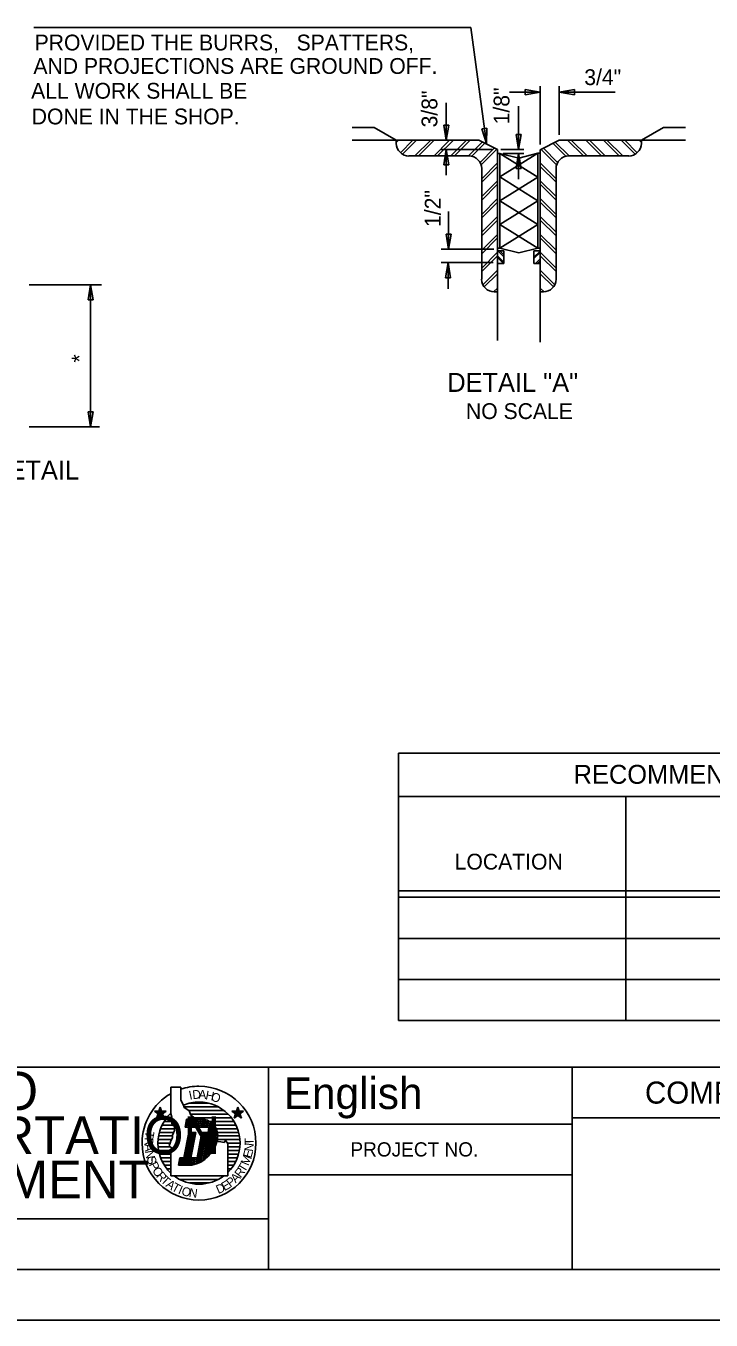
# Model space of a CAD drawing. Extents: x 0 to 11.3, y 0 to 7.8.
# Drawn here: x 5.617 to 7.875, y 0 to 4.265 of the extents above; entities that cross this region are included whole.
import ezdxf

# ---------------------------------------------------------------- set-up
doc = ezdxf.new("R2010")
doc.units = 0
for name, color, linetype in [('BORDER_ANNO_Cutsheet', 7, 'Continuous'), ('BRDG_ANNO_Anno-Sheet', 7, 'Continuous'), ('BRDG_ANNO_General-Notes', 7, 'Continuous'), ('BRDG_BASE_Obj-Line', 7, 'Continuous'), ('BRDG_BASE_Pattern', 7, 'Continuous')]:
    doc.layers.add(name, color=color, linetype=linetype)

msp = doc.modelspace()

# ---------------------------------------------------------------- linework, layer by layer
at = {"layer": 'BORDER_ANNO_Cutsheet'}
msp.add_lwpolyline([(0, 7.3333), (11.3333, 7.3333), (11.3333, 0), (0, 0)], close=True, dxfattribs=at)
at = {"layer": 'BRDG_ANNO_Anno-Sheet'}
for p, q in [((0.5, 0.8333), (6.4167, 0.8333)), ((6.4167, 0.1667), (6.4167, 0.8333)), ((6.4167, 0.8333), (11.1667, 0.8333)), ((7.4167, 0.1667), (7.4167, 0.8333)), ((6.0948, 0.6808), (6.0948, 0.7677)), ((6.0948, 0.7677), (6.1277, 0.7677)), ((6.1277, 0.7244), (6.1277, 0.7677)), ((6.0671, 0.68), (6.0408, 0.6885)), ((6.0552, 0.6885), (6.0408, 0.6885)), ((6.0525, 0.68), (6.0408, 0.6885)), ((6.0644, 0.6885), (6.0479, 0.666)), ((6.0525, 0.68), (6.079, 0.6885)), ((6.0552, 0.6885), (6.0598, 0.7023)), ((6.0552, 0.6885), (6.0717, 0.666)), ((6.0598, 0.6746), (6.0598, 0.7023)), ((6.0644, 0.6885), (6.0598, 0.7023)), ((6.0644, 0.6885), (6.079, 0.6885)), ((6.0671, 0.68), (6.079, 0.6885)), ((6.1277, 0.7244), (6.1365, 0.7087)), ((6.1365, 0.7087), (6.1381, 0.7017)), ((6.1381, 0.7017), (6.1554, 0.6896)), ((6.139, 0.7027), (6.2502, 0.7027)), ((6.155, 0.7148), (6.2194, 0.7148)), ((6.155, 0.6908), (6.269, 0.6908)), ((6.1554, 0.6896), (6.1608, 0.6756)), ((6.3225, 0.68), (6.296, 0.6885)), ((6.3079, 0.68), (6.296, 0.6885)), ((6.3106, 0.6885), (6.296, 0.6885)), ((6.3198, 0.6885), (6.3033, 0.666)), ((6.3079, 0.68), (6.3342, 0.6885)), ((6.3106, 0.6885), (6.3152, 0.7023)), ((6.3106, 0.6885), (6.3271, 0.666)), ((6.3152, 0.6746), (6.3152, 0.7023)), ((6.3198, 0.6885), (6.3152, 0.7023)), ((6.3198, 0.6885), (6.3342, 0.6885)), ((6.3225, 0.68), (6.3342, 0.6885)), ((6.0525, 0.68), (6.0479, 0.666)), ((6.0598, 0.6746), (6.0479, 0.666)), ((6.0598, 0.6746), (6.0717, 0.666)), ((6.0656, 0.6427), (6.0994, 0.6427)), ((6.0671, 0.68), (6.0717, 0.666)), ((6.0723, 0.6548), (6.0975, 0.6548)), ((6.0806, 0.6669), (6.0979, 0.6669)), ((6.0915, 0.6787), (6.0954, 0.6787)), ((6.0981, 0.6687), (6.0948, 0.6808)), ((6.0981, 0.6583), (6.0981, 0.6687)), ((6.0981, 0.6496), (6.0981, 0.6583)), ((6.1, 0.6427), (6.0981, 0.6496)), ((6.1069, 0.6392), (6.1, 0.6427)), ((6.1417, 0.6356), (6.1469, 0.6619)), ((6.1465, 0.6356), (6.1513, 0.6619)), ((6.1469, 0.6619), (6.2042, 0.6619)), ((6.1517, 0.6356), (6.1567, 0.6619)), ((6.1571, 0.6356), (6.1619, 0.6619)), ((6.1596, 0.6787), (6.2835, 0.6787)), ((6.1608, 0.6756), (6.1781, 0.6619)), ((6.1623, 0.6356), (6.1673, 0.6619)), ((6.1675, 0.6356), (6.1725, 0.6619)), ((6.1719, 0.6669), (6.2942, 0.6669)), ((6.1729, 0.6356), (6.1777, 0.6619)), ((6.1781, 0.6356), (6.1831, 0.6619)), ((6.1835, 0.6356), (6.1883, 0.6619)), ((6.1887, 0.6356), (6.1937, 0.6619)), ((6.1942, 0.6356), (6.199, 0.6619)), ((6.1994, 0.6356), (6.2044, 0.6619)), ((6.1998, 0.5248), (6.224, 0.654)), ((6.2046, 0.6356), (6.2094, 0.6604)), ((6.2058, 0.5285), (6.2287, 0.6506)), ((6.21, 0.6356), (6.2144, 0.659)), ((6.2121, 0.5335), (6.2331, 0.6462)), ((6.2152, 0.6356), (6.2192, 0.6567)), ((6.2185, 0.5396), (6.2375, 0.6415)), ((6.2229, 0.6548), (6.3025, 0.6548)), ((6.2367, 0.6427), (6.3092, 0.6427)), ((6.3079, 0.68), (6.3033, 0.666)), ((6.3152, 0.6746), (6.3033, 0.666)), ((6.3152, 0.6746), (6.3271, 0.666)), ((6.3225, 0.68), (6.3271, 0.666)), ((6.4167, 0.6458), (7.4167, 0.6458)), ((7.4167, 0.6667), (10.0833, 0.6667)), ((6.0542, 0.6069), (6.0994, 0.6069)), ((6.0569, 0.6188), (6.1037, 0.6188)), ((6.0604, 0.6308), (6.1063, 0.6308)), ((6.0948, 0.5906), (6.1, 0.601)), ((6.1, 0.6096), (6.1033, 0.6167)), ((6.1, 0.601), (6.1, 0.6096)), ((6.1033, 0.6167), (6.1069, 0.6252)), ((6.1069, 0.6304), (6.1069, 0.6392)), ((6.1069, 0.6252), (6.1069, 0.6304)), ((6.1381, 0.535), (6.1537, 0.6183)), ((6.1387, 0.5106), (6.159, 0.6183)), ((6.2204, 0.6356), (6.1417, 0.6356)), ((6.1442, 0.5106), (6.1644, 0.6183)), ((6.1494, 0.5106), (6.1696, 0.6183)), ((6.1537, 0.6183), (6.1767, 0.6183)), ((6.1548, 0.5106), (6.175, 0.6183)), ((6.1767, 0.6183), (6.161, 0.535)), ((6.1812, 0.535), (6.1969, 0.6183)), ((6.1823, 0.5158), (6.2015, 0.6183)), ((6.1879, 0.5183), (6.2067, 0.6183)), ((6.1937, 0.521), (6.2121, 0.6183)), ((6.1969, 0.6183), (6.2173, 0.6183)), ((6.2173, 0.6183), (6.2204, 0.6356)), ((6.2252, 0.5467), (6.2417, 0.6354)), ((6.2323, 0.5563), (6.2456, 0.6273)), ((6.2406, 0.5725), (6.2485, 0.615)), ((6.2442, 0.6308), (6.3144, 0.6308)), ((6.2481, 0.6188), (6.3181, 0.6188)), ((6.2492, 0.6069), (6.3208, 0.6069)), ((6.0521, 0.5827), (6.0925, 0.5827)), ((6.0525, 0.5948), (6.0969, 0.5948)), ((6.0527, 0.5708), (6.0938, 0.5708)), ((6.0544, 0.5587), (6.0994, 0.5587)), ((6.0896, 0.575), (6.0929, 0.5835)), ((6.0948, 0.5698), (6.0896, 0.575)), ((6.0929, 0.5835), (6.0948, 0.5906)), ((6.0981, 0.5646), (6.0948, 0.5698)), ((6.0948, 0.5506), (6.1, 0.5558)), ((6.1, 0.561), (6.0981, 0.5646)), ((6.1, 0.5558), (6.1, 0.561)), ((6.2469, 0.5925), (6.2494, 0.5887)), ((6.2475, 0.5948), (6.3225, 0.5948)), ((6.2494, 0.5887), (6.2598, 0.5871)), ((6.2598, 0.5871), (6.2702, 0.5854)), ((6.2702, 0.5854), (6.2754, 0.5923)), ((6.2754, 0.5923), (6.2823, 0.5819)), ((6.2817, 0.5827), (6.3229, 0.5827)), ((6.2823, 0.5819), (6.2823, 0.4758)), ((6.2823, 0.5587), (6.3206, 0.5587)), ((6.2825, 0.5708), (6.3223, 0.5708)), ((6.0571, 0.5469), (6.0946, 0.5469)), ((6.0612, 0.5348), (6.0942, 0.5348)), ((6.0665, 0.5227), (6.0942, 0.5227)), ((6.0948, 0.4758), (6.0948, 0.5506)), ((6.1198, 0.5106), (6.1244, 0.535)), ((6.1229, 0.5106), (6.1275, 0.535)), ((6.1244, 0.535), (6.1381, 0.535)), ((6.1283, 0.5106), (6.1329, 0.535)), ((6.1335, 0.5106), (6.1381, 0.535)), ((6.16, 0.5106), (6.1646, 0.535)), ((6.161, 0.535), (6.1812, 0.535)), ((6.1654, 0.5108), (6.17, 0.535)), ((6.171, 0.5123), (6.1752, 0.535)), ((6.1767, 0.514), (6.1804, 0.535)), ((6.2823, 0.5469), (6.3179, 0.5469)), ((6.2823, 0.5348), (6.3137, 0.5348)), ((6.2823, 0.5227), (6.3083, 0.5227)), ((6.0733, 0.5108), (6.0944, 0.5108)), ((6.0819, 0.4987), (6.0942, 0.4987)), ((6.0925, 0.4869), (6.0946, 0.4869)), ((6.2823, 0.4758), (6.0948, 0.4758)), ((6.1642, 0.5106), (6.1198, 0.5106)), ((6.2823, 0.5108), (6.3017, 0.5108)), ((6.2823, 0.4987), (6.2933, 0.4987)), ((6.4167, 0.4792), (7.4167, 0.4792)), ((6.2502, 0.4637), (6.124, 0.4637)), ((6.2196, 0.4519), (6.1558, 0.4519)), ((4.6667, 0.3333), (6.4167, 0.3333))]:
    msp.add_line(p, q, dxfattribs=at)
msp.add_lwpolyline([(0.5, 7.1667), (11.1667, 7.1667), (11.1667, 0.1667), (0.5, 0.1667)], close=True, dxfattribs=at)
for centre, radius, start, end in [((6.1875, 0.5833), 0.1875, 90, 108.596), ((6.1875, 0.5833), 0.1875, 0, 90), ((6.1875, 0.5833), 0.1875, 119.6331, 180), ((6.1875, 0.5833), 0.1354, 90, 112.1452), ((6.1875, 0.5833), 0.1354, 0, 90), ((6.1875, 0.5833), 0.1354, 133.1926, 180), ((6.1944, 0.608), 0.0547, 343.4981, 79.7362), ((6.1875, 0.5833), 0.1875, 180, 270), ((6.1875, 0.5833), 0.1354, 180.2644, 226.7946), ((6.145, 0.6127), 0.1039, 280.6479, 348.7719), ((6.1875, 0.5833), 0.1875, 270, 0), ((6.1875, 0.5833), 0.1354, 314.427, 0), ((6.1875, 0.5833), 0.1354, 232.5658, 270), ((6.1875, 0.5833), 0.1354, 270, 307.4536)]:
    msp.add_arc(centre, radius, start, end, dxfattribs=at)
at = {"layer": 'BRDG_ANNO_General-Notes'}
for p, q in [((5.6436, 4.2598), (7.0836, 4.2598)), ((7.0836, 4.2598), (7.1347, 3.878)), ((7.2617, 4.0384), (7.2617, 4.0551)), ((7.2617, 4.0551), (7.3117, 4.0467)), ((7.3117, 3.8745), (7.3117, 4.0671)), ((7.3744, 3.9059), (7.3744, 4.0671)), ((7.3744, 4.0467), (7.4244, 4.0551)), ((7.4244, 4.0551), (7.4244, 4.0384)), ((7.002, 3.8885), (7.002, 4.0116)), ((7.2101, 4.0467), (7.3117, 4.0467)), ((7.3117, 4.0467), (7.2617, 4.0384)), ((7.3744, 4.0467), (7.5586, 4.0467)), ((7.4244, 4.0384), (7.3744, 4.0467)), ((7.2403, 3.8577), (7.2403, 4.0012)), ((6.9937, 3.9385), (7.0104, 3.9385)), ((7.002, 3.8885), (6.9937, 3.9385)), ((7.0104, 3.9385), (7.002, 3.8885)), ((7.1198, 3.9265), (7.1363, 3.9287)), ((7.1347, 3.878), (7.1198, 3.9265)), ((7.1363, 3.9287), (7.1347, 3.878)), ((7.232, 3.9077), (7.2486, 3.9077)), ((7.2403, 3.8577), (7.232, 3.9077)), ((7.2486, 3.9077), (7.2403, 3.8577)), ((7.1535, 3.8577), (6.9847, 3.8577)), ((6.9937, 3.8077), (7.002, 3.8577)), ((7.002, 3.7738), (7.002, 3.8577)), ((7.002, 3.8577), (7.0104, 3.8077)), ((7.1818, 3.8577), (7.2577, 3.8577)), ((7.1897, 3.8451), (7.2577, 3.8451)), ((7.232, 3.7951), (7.2403, 3.8451)), ((7.2403, 3.76), (7.2403, 3.8451)), ((7.2403, 3.8451), (7.2486, 3.7951)), ((7.0104, 3.8077), (6.9937, 3.8077)), ((7.2486, 3.7951), (7.232, 3.7951)), ((7.0098, 3.529), (7.0098, 3.6537)), ((7.0015, 3.579), (7.0181, 3.579)), ((7.0098, 3.529), (7.0015, 3.579)), ((7.0181, 3.579), (7.0098, 3.529)), ((6.9852, 3.529), (7.1584, 3.529)), ((6.9852, 3.4854), (7.1568, 3.4854)), ((6.9999, 3.4354), (7.0082, 3.4854)), ((7.0082, 3.3992), (7.0082, 3.4854)), ((7.0082, 3.4854), (7.0166, 3.4354)), ((5.6277, 3.4122), (5.8667, 3.4122)), ((5.8219, 3.3622), (5.8303, 3.4122)), ((5.8303, 3.4122), (5.8303, 2.9434)), ((5.8303, 3.4122), (5.8386, 3.3622)), ((7.0166, 3.4354), (6.9999, 3.4354)), ((5.8386, 3.3622), (5.8219, 3.3622)), ((5.8219, 2.9934), (5.8386, 2.9934)), ((5.8303, 2.9434), (5.8219, 2.9934)), ((5.8386, 2.9934), (5.8303, 2.9434)), ((5.6277, 2.9434), (5.8601, 2.9434)), ((6.8443, 0.987), (6.8443, 1.8683)), ((6.8443, 1.8683), (11.0168, 1.8683)), ((11.0168, 1.7259), (6.8443, 1.7259)), ((7.5943, 0.987), (7.5943, 1.7259)), ((6.8443, 1.4143), (11.0168, 1.4143)), ((11.0168, 1.3935), (6.8443, 1.3935)), ((6.8443, 1.2579), (11.0168, 1.2579)), ((11.0168, 1.1224), (6.8443, 1.1224)), ((6.8443, 0.987), (11.0168, 0.987))]:
    msp.add_line(p, q, dxfattribs=at)
at = {"layer": 'BRDG_BASE_Obj-Line'}
for p, q in [((6.7647, 3.9302), (6.6918, 3.9302)), ((6.8376, 3.8885), (6.7647, 3.9302)), ((7.6451, 3.8885), (7.718, 3.9302)), ((7.718, 3.9302), (7.7907, 3.9302)), ((6.8376, 3.8885), (6.6918, 3.8885)), ((6.8376, 3.8885), (7.1092, 3.8885)), ((6.8376, 3.8781), (6.8376, 3.8885)), ((7.1092, 3.8885), (7.1709, 3.8577)), ((7.3744, 3.8885), (7.3117, 3.8572)), ((7.6451, 3.8885), (7.3744, 3.8885)), ((7.6451, 3.8885), (7.7907, 3.8885)), ((7.6451, 3.8781), (7.6451, 3.8885)), ((7.1709, 3.8577), (7.1709, 3.3886)), ((7.3117, 3.8572), (7.3117, 3.3886)), ((7.0772, 3.8365), (6.8793, 3.8365)), ((6.9418, 3.8365), (6.9418, 3.8365)), ((7.4055, 3.8365), (7.6034, 3.8365)), ((7.5409, 3.8365), (7.5409, 3.8365)), ((7.1189, 3.4303), (7.1189, 3.7948)), ((7.3638, 3.4303), (7.3638, 3.7948)), ((7.1189, 3.4927), (7.1189, 3.4927)), ((7.3638, 3.4927), (7.3638, 3.4927)), ((7.1709, 3.3886), (7.1605, 3.3886)), ((7.1709, 3.3886), (7.1709, 3.2281)), ((7.3117, 3.3886), (7.3117, 3.2229)), ((7.3117, 3.3886), (7.3221, 3.3886))]:
    msp.add_line(p, q, dxfattribs=at)
for points in [[(7.1709, 3.8451), (7.1787, 3.8451), (7.1787, 3.5326), (7.1709, 3.5326)], [(7.3039, 3.8455), (7.3117, 3.8455), (7.3117, 3.533), (7.3039, 3.533)], [(7.1709, 3.5243), (7.1709, 3.4827), (7.1917, 3.4827), (7.1917, 3.5243)], [(7.2909, 3.5239), (7.2909, 3.4822), (7.3117, 3.4822), (7.3117, 3.5239)]]:
    msp.add_lwpolyline(points, close=True, dxfattribs=at)
for centre, start, end in [((6.8793, 3.8781), 180, 270), ((7.6033, 3.8781), 270, 0), ((7.0772, 3.7948), 0, 90), ((7.4055, 3.7948), 90, 180), ((7.1605, 3.4302), 180, 270), ((7.3221, 3.4302), 270, 0)]:
    msp.add_arc(centre, 0.0417, start, end, dxfattribs=at)
at = {"layer": 'BRDG_BASE_Pattern'}
for p, q in [((7.0757, 3.8365), (7.121, 3.8818)), ((7.4069, 3.8365), (7.3614, 3.882)), ((7.0864, 3.8354), (7.1294, 3.8784)), ((7.1134, 3.8153), (7.1603, 3.8622)), ((7.1787, 3.8451), (7.2412, 3.8295)), ((7.1787, 3.8451), (7.3037, 3.767)), ((7.3039, 3.8455), (7.1789, 3.7673)), ((7.2412, 3.8297), (7.3039, 3.8455)), ((7.3692, 3.8153), (7.3228, 3.8617)), ((7.3962, 3.8354), (7.3534, 3.8782)), ((7.3037, 3.767), (7.1787, 3.6889)), ((7.1789, 3.7673), (7.3039, 3.6892)), ((7.1787, 3.6889), (7.3037, 3.6107)), ((7.3039, 3.6892), (7.1789, 3.6111)), ((7.3037, 3.6107), (7.1787, 3.5326)), ((7.1789, 3.6111), (7.3039, 3.533)), ((7.1787, 3.5326), (7.2412, 3.517)), ((7.3037, 3.5332), (7.2412, 3.5176))]:
    msp.add_line(p, q, dxfattribs=at)
for points in [[(6.8376, 3.8811), (6.8449, 3.8885)], [(6.851, 3.8474), (6.8921, 3.8885)], [(6.8577, 3.8424), (6.9039, 3.8885)], [(6.899, 3.8365), (6.951, 3.8885)], [(6.9107, 3.8365), (6.9628, 3.8885)], [(6.961, 3.8363), (7.0118, 3.8871)], [(6.9749, 3.8378), (7.0256, 3.8885)], [(7.018, 3.8378), (7.0689, 3.8885)], [(7.0305, 3.8384), (7.0806, 3.8885)], [(7.4528, 3.8378), (7.402, 3.8885)], [(7.4659, 3.8365), (7.4138, 3.8885)], [(7.5141, 3.8365), (7.462, 3.8885)], [(7.5272, 3.8357), (7.4752, 3.8878)], [(7.5719, 3.8365), (7.5198, 3.8885)], [(7.5837, 3.8365), (7.5316, 3.8885)], [(7.6249, 3.8424), (7.5788, 3.8885)], [(7.6316, 3.8474), (7.5906, 3.8885)], [(7.6451, 3.8811), (7.6377, 3.8885)], [(7.117, 3.807), (7.1686, 3.8587)], [(7.3657, 3.807), (7.3146, 3.8581)], [(7.1189, 3.7617), (7.1709, 3.8139)], [(7.1189, 3.7499), (7.1709, 3.8021)], [(7.3638, 3.7617), (7.3117, 3.8139)], [(7.3638, 3.7499), (7.3117, 3.8021)], [(7.1189, 3.7028), (7.1709, 3.7549)], [(7.3638, 3.7028), (7.3117, 3.7549)], [(7.1189, 3.691), (7.1709, 3.7431)], [(7.3638, 3.691), (7.3117, 3.7431)], [(7.1189, 3.644), (7.1709, 3.696)], [(7.1189, 3.6321), (7.1709, 3.6842)], [(7.3638, 3.644), (7.3117, 3.696)], [(7.3638, 3.6321), (7.3117, 3.6842)], [(7.1189, 3.585), (7.1709, 3.6371)], [(7.3638, 3.585), (7.3117, 3.6371)], [(7.1189, 3.5732), (7.1709, 3.6253)], [(7.3638, 3.5732), (7.3117, 3.6253)], [(7.1189, 3.526), (7.1709, 3.5781)], [(7.1189, 3.5143), (7.1709, 3.5664)], [(7.3638, 3.526), (7.3117, 3.5781)], [(7.3638, 3.5143), (7.3117, 3.5664)], [(7.1189, 3.4671), (7.1709, 3.5193)], [(7.1189, 3.4554), (7.1709, 3.5075)], [(7.1917, 3.4863), (7.1709, 3.5072)], [(7.1903, 3.4827), (7.1709, 3.5021)], [(7.1917, 3.5046), (7.172, 3.5243)], [(7.1917, 3.5112), (7.1786, 3.5243)], [(7.2909, 3.5026), (7.3114, 3.5231)], [(7.2909, 3.4982), (7.3115, 3.5189)], [(7.2961, 3.4822), (7.3114, 3.4975)], [(7.3638, 3.4671), (7.3117, 3.5193)], [(7.3638, 3.4554), (7.3117, 3.5075)], [(7.1229, 3.4123), (7.1698, 3.4593)], [(7.3023, 3.4822), (7.3114, 3.4912)], [(7.3597, 3.4123), (7.3117, 3.4604)], [(7.1274, 3.4051), (7.1709, 3.4485)], [(7.3552, 3.4051), (7.3117, 3.4485)], [(7.1582, 3.3887), (7.1709, 3.4014)], [(7.3244, 3.3887), (7.3117, 3.4014)]]:
    msp.add_lwpolyline(points, dxfattribs=at)

# ---------------------------------------------------------------- texts
at = {"layer": 'BRDG_ANNO_Anno-Sheet'}
for s, height, p in [('IDAHO', 0.125, (5.1279, 0.6927)), ('English', 0.10417, (6.4669, 0.6956)), ('COMPRESSION SEAL EXPANSION JOINT', 0.072709, (7.6569, 0.7135)), ('TRANSPORTATION', 0.125, (4.7156, 0.5469)), ('PROJECT NO.', 0.046875, (6.6864, 0.5392)), ('DEPARTMENT', 0.125, (4.8731, 0.401))]:
    msp.add_text(s, height=height, dxfattribs=at).set_placement(p)
for s, rotation, p in [('I', 11.9519, (6.1573, 0.726)), ('D', 5.2118, (6.1671, 0.7281)), ('A', 357.8718, (6.1856, 0.7294)), ('H', 349.6318, (6.2073, 0.7279)), ('O', 342.1917, (6.2248, 0.7244)), ('R', 266.0275, (6.0088, 0.6025)), ('T', 259.4265, (6.0127, 0.6252)), ('T', 90.4926, (6.3673, 0.5765)), ('A', 273.764, (6.0077, 0.5802)), ('N', 280.3758, (6.0096, 0.5571)), ('E', 75.6105, (6.3598, 0.5323)), ('N', 83.1932, (6.365, 0.5544)), ('S', 287.9279, (6.0144, 0.5346)), ('P', 295.4976, (6.0219, 0.5135)), ('T', 59.0362, (6.3379, 0.485)), ('M', 67.7139, (6.3502, 0.5069)), ('O', 302.6446, (6.0319, 0.4933)), ('R', 309.9079, (6.0446, 0.4742)), ('T', 317.1211, (6.0592, 0.4571)), ('P', 37.6656, (6.291, 0.4365)), ('A', 45, (6.3085, 0.4502)), ('R', 52.3344, (6.3246, 0.4671)), ('A', 324.6375, (6.076, 0.4419)), ('T', 331.7503, (6.0948, 0.429)), ('I', 337.0213, (6.1165, 0.4179)), ('O', 343.3287, (6.1275, 0.4135)), ('N', 351.6598, (6.1529, 0.4067)), ('D', 22.9887, (6.251, 0.4152)), ('E', 30.5476, (6.2719, 0.4246))]:
    msp.add_text(s, height=0.029, rotation=rotation, dxfattribs=at).set_placement(p)
at = {"layer": 'BRDG_ANNO_General-Notes'}
for s, height, p in [('PROVIDED THE BURRS,   SPATTERS,', 0.052083, (5.6461, 4.1843)), ('AND PROJECTIONS ARE GROUND OFF.', 0.052083, (5.642, 4.1071)), ('3/4"', 0.05208, (7.457, 4.0702)), ('ALL WORK SHALL BE', 0.052083, (5.6345, 4.0253)), ('DONE IN THE SHOP.', 0.052083, (5.6365, 3.9406)), ('DETAIL "A"', 0.0625, (7.0057, 3.0591)), ('NO SCALE', 0.05208, (7.0671, 2.9696)), ('JOINT SEAL DETAIL', 0.0625, (4.9981, 2.7701)), ('RECOMMENDED MANUFACTURERS OF THE SHOWN JOINT ASSEMBLY', 0.0625, (7.4221, 1.7674)), ('LOCATION', 0.05208, (7.0299, 1.4848))]:
    msp.add_text(s, height=height, dxfattribs=at).set_placement(p)
for s, height, p in [('1/8"', 0.05208, (7.2104, 3.9407)), ('3/8"', 0.05208, (6.9728, 3.9307)), ('1/2"', 0.05208, (6.9836, 3.6026)), ('*', 0.0521, (5.8199, 3.1557))]:
    msp.add_text(s, height=height, rotation=90, dxfattribs=at).set_placement(p)

doc.saveas('drawing.dxf')
